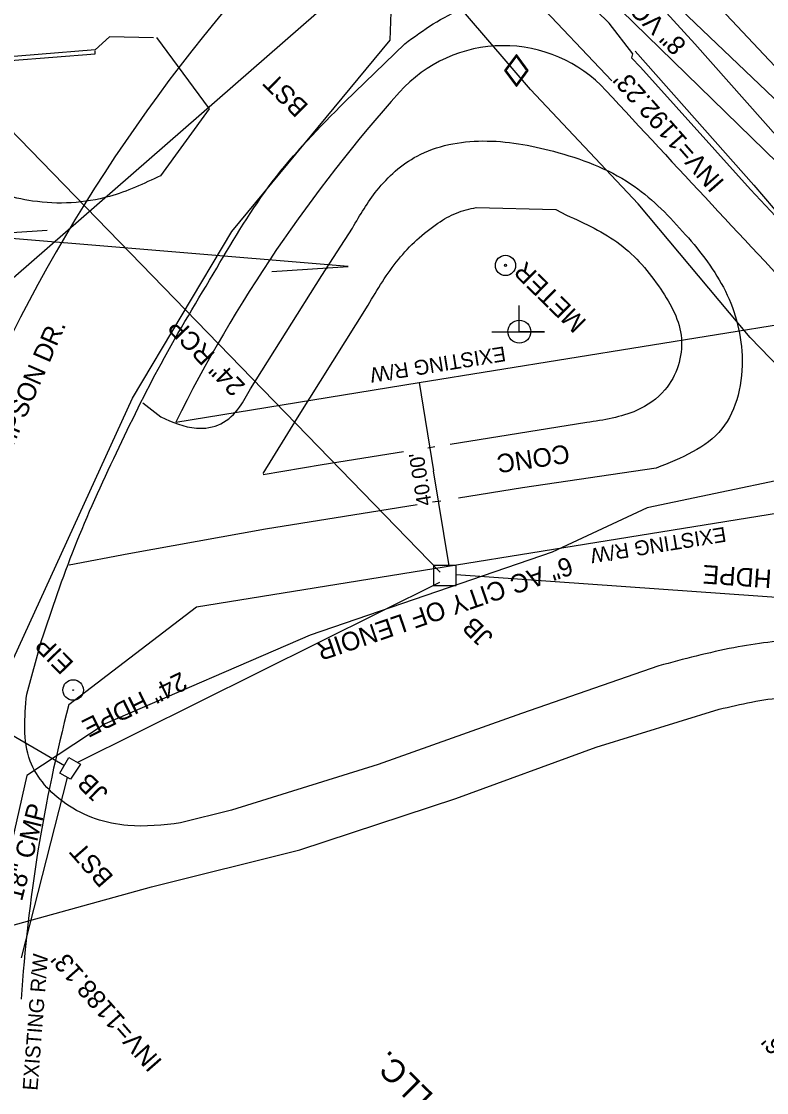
# Model space of a CAD drawing. Extents: x 1263837 to 1268319, y 770628 to 773628.
# Drawn here: x 1266461.1 to 1266621.4, y 771971.5 to 772202.1 of the extents above; entities that cross this region are included whole.
import ezdxf

# ---------------------------------------------------------------- set-up
doc = ezdxf.new("R2010")
doc.units = 0
for name, color, linetype in [('Exist Building', 7, 'Continuous'), ('Exist Property Iron Pin Text', 7, 'Continuous'), ('Exist Property Same Owner Line CELL', 7, 'Continuous'), ('Exist Roads EOP Other', 7, 'Continuous'), ('Exist Roads EOP Other Text', 7, 'Continuous'), ('Exist Roads EOP Text', 7, 'Continuous'), ('Exist Roads EOT Text', 7, 'Continuous'), ('Exist Structure Minor Catch Basin Top Elevation', 7, 'Continuous'), ('Exist Structure Minor Junction Box', 7, 'Continuous'), ('Exist Structure Minor Junction Box Text', 7, 'Continuous'), ('Exist Structure Minor Pipes HDPE 24 Inch', 7, 'Continuous'), ('Exist Structure Minor Pipes HDPE 24 Inch Text', 7, 'Continuous'), ('Exist Structure Minor Pipes RCP 24 Inch', 7, 'Continuous'), ('Exist Structure Minor Pipes RCP 24 Inch Text', 7, 'Continuous'), ('Exist Utilities Gas UG Line SUE LOS B', 7, 'Continuous'), ('Exist Utilities Gas UG Line SUE LOS C', 7, 'Continuous'), ('Exist Utilities Gas Valve CELL', 7, 'Continuous'), ('Exist Utilities Other Located Object CELL', 7, 'Continuous'), ('Exist Utilities Other Located Object Text', 7, 'Continuous'), ('Exist Utilities Power Joint Use Telephone CELL', 7, 'Continuous'), ('Exist Utilities Water UG Line SUE LOS B', 7, 'Continuous'), ('Exist Utilities Water UG Line SUE LOS B Text', 7, 'Continuous'), ('Prop Conc 4in Sidewalk', 7, 'Continuous'), ('Prop Drainage Structure Pipe Alternate 42in Label', 7, 'Continuous'), ('Prop Drainage Structure Pipe RCP 30in Class III Label', 7, 'Continuous'), ('Prop Drainage Structure Pipe RCP 42in Class III', 7, 'Continuous'), ('Prop Drainage Structure Plot Symbol 20 Scale CELL', 7, 'Continuous'), ('Prop Earthen Structure Base Ditch Special Cut with Rip Rap Detail CELL', 7, 'Continuous'), ('Prop Earthen Structure V Ditch Special Lateral with Rip Rap Detail CELL', 7, 'Continuous'), ('Prop Horizontal Alignment', 7, 'Continuous'), ('Prop SS Fill Text', 7, 'Continuous'), ('Prop SS Transition Line', 7, 'Continuous'), ('Scratch_Level_0', 7, 'Continuous'), ('Scratch_Level_2', 7, 'Continuous'), ('Scratch_Level_5', 7, 'Continuous')]:
    doc.layers.add(name, color=color, linetype=linetype)

# ---------------------------------------------------------------- blocks, each defined once
blk = doc.blocks.new('EXIST PROPERTY IRON PIN')
at = {"layer": 'Prop Conc 4in Sidewalk'}
for radius in [0.0441, 0.00141]:
    blk.add_circle((0, 0), radius, dxfattribs=at)
blk = doc.blocks.new('EXIST UTILITIES POWER JOINT USE TELEPHONE')
at = {"layer": 'Exist Utilities Power Joint Use Telephone CELL'}
blk.add_line((0, 0), (0, 0), dxfattribs=at)
blk.add_lwpolyline([(-0.1188, 0), (0.108, -0.0008), (0, -0.0004), (0, 0.1125)], dxfattribs=at)
blk.add_circle((0, 0.0001), 0.049, dxfattribs=at)
blk = doc.blocks.new('EXIST UTILITIES GAS VALVE')
at = {"layer": 'Exist Utilities Gas Valve CELL'}
blk.add_line((0, 0), (0, 0), dxfattribs=at)
blk.add_lwpolyline([(0, 0.0683), (-0.0508, 0), (0, -0.0683), (0.0508, 0), (0, 0.0683)], dxfattribs=at)
blk.add_lwpolyline([(0.0458, 0), (0, 0.0615), (-0.0458, 0), (0, -0.0615)], close=True, dxfattribs=at)

msp = doc.modelspace()

# ---------------------------------------------------------------- linework, layer by layer
at = {"layer": 'Exist Building'}
msp.add_lwpolyline([(1266342.06, 772185.13), (1266342.08, 772184.54), (1266374.13, 772186.64), (1266407.27, 772189.04), (1266438.37, 772191.77), (1266458.75, 772193.68), (1266476.96, 772195.16), (1266476.92, 772195.76)], dxfattribs=at)
at = {"layer": 'Exist Property Same Owner Line CELL'}
msp.add_lwpolyline([(1266514.94, 772148.26), (1266531.34, 772149.34), (1266450.24, 772156.1), (1266466.63, 772157.18)], dxfattribs=at)
at = {"layer": 'Exist Roads EOP Other'}
for p, q in [((1266558.93, 772162.08), (1266576.01, 772161.65)), ((1266576.01, 772161.65), (1266578.36, 772160.42)), ((1266525.69, 772147.43), (1266532.28, 772157.65)), ((1266510.32, 772123.05), (1266525.69, 772147.43)), ((1266487.17, 772119.99), (1266491.09, 772116.97))]:
    msp.add_line(p, q, dxfattribs=at)
for points in [[(1266513.08, 772104.83), (1266520.46, 772116.81), (1266535.65, 772141.04)], [(1266582.68, 772115.76), (1266553.29, 772111.06)], [(1266543.25, 772109.45), (1266525.78, 772106.66), (1266513.11, 772104.55)], [(1266550.02, 772110.53), (1266548.5, 772110.29)], [(1266597.62, 772105.95), (1266568.85, 772101.69), (1266555.13, 772099.5)], [(1266546.23, 772098.07), (1266538.18, 772096.78), (1266513.57, 772092.83), (1266484.19, 772087.52), (1266471.34, 772085.06)], [(1266551.27, 772098.88), (1266549.54, 772098.6)]]:
    msp.add_lwpolyline(points, dxfattribs=at)
for points in [[(1266532.28, 772157.65), (1266537.56, 772165.75), (1266546.19, 772173.14), (1266560.29, 772176.38), (1266575.57, 772174.16), (1266592.13, 772167.17), (1266603.32, 772156.92), (1266612.09, 772144.88), (1266616.12, 772130.18), (1266611.75, 772114.39), (1266597.62, 772105.95)], [(1266535.65, 772141.04), (1266542.18, 772150.88), (1266550.67, 772158.68), (1266554.64, 772160.87), (1266558.93, 772162.08)], [(1266578.36, 772160.42), (1266589.8, 772154.19), (1266598.61, 772144.5), (1266603.07, 772133.85), (1266599.52, 772122.82), (1266593.43, 772118.38), (1266582.68, 772115.76)], [(1266491.09, 772116.97), (1266498.71, 772114.56), (1266503.97, 772115.5), (1266508, 772119.08), (1266510.32, 772123.05)]]:
    msp.add_spline(points, degree=3, dxfattribs=at)
at = {"layer": 'Exist Structure Minor Junction Box'}
msp.add_lwpolyline([(1266549.75, 772085.02), (1266549.75, 772080.7), (1266554.62, 772080.7), (1266554.62, 772085.02)], close=True, dxfattribs=at)
msp.add_lwpolyline([(1266469.34, 772040.28), (1266471.25, 772043.64), (1266473.76, 772042.21), (1266471.64, 772038.98), (1266469.34, 772040.28)], dxfattribs=at)
at = {"layer": 'Exist Structure Minor Pipes HDPE 24 Inch'}
for p, q in [((1266694.5, 772073.08), (1266554.62, 772082.96)), ((1266551.03, 772081.34), (1266473.12, 772042.57))]:
    msp.add_line(p, q, dxfattribs=at)
at = {"layer": 'Exist Structure Minor Pipes RCP 24 Inch'}
msp.add_line((1266455.77, 772181.85), (1266551.14, 772083.59), dxfattribs=at)
at = {"layer": 'Exist Utilities Gas UG Line SUE LOS B'}
msp.add_line((1266542.76, 772219.73), (1266372.53, 772071.1), dxfattribs=at)
msp.add_lwpolyline([(1266634.89, 772116.41), (1266617.88, 772134.08), (1266593.74, 772162.87), (1266570.59, 772187.5), (1266552.2, 772208.93), (1266533.9, 772229.88), (1266520.79, 772243.67), (1266506.09, 772258.4), (1266476.3, 772293.88), (1266450.61, 772322.46), (1266432.17, 772342.72), (1266403.52, 772374.96), (1266376.24, 772400.79), (1266349.14, 772427.18), (1266329.27, 772447.31), (1266306.87, 772470.18), (1266286, 772492.58), (1266264.53, 772515.83), (1266241.63, 772542.64), (1266214.18, 772573.35), (1266190.07, 772598.41)], dxfattribs=at)
at = {"layer": 'Exist Utilities Gas UG Line SUE LOS C'}
msp.add_lwpolyline([(1266457.07, 772059.93), (1266485, 772121.03), (1266506.31, 772156.87), (1266540.43, 772198.08), (1266541.09, 772218.23), (1266505.13, 772257.1), (1266475.32, 772292.21), (1266449.64, 772321.32), (1266402.45, 772373.22), (1266377.36, 772397.1)], dxfattribs=at)
at = {"layer": 'Exist Utilities Other Located Object CELL'}
for radius in [2.18, 0.24]:
    msp.add_circle((1266565.21, 772149.59), radius, dxfattribs=at)
at = {"layer": 'Exist Utilities Water UG Line SUE LOS B'}
for points in [[(1266813.73, 772072.54), (1266793.78, 772088.05), (1266755.27, 772103.69), (1266718.33, 772109.44), (1266678.54, 772111.01), (1266653.19, 772143.96), (1266605.92, 772197.31), (1266538.03, 772271.69), (1266479.88, 772335.62), (1266421.78, 772389.51), (1266357.3, 772412.97), (1266321.15, 772412.43), (1266255.77, 772387.79), (1266212.97, 772357.83), (1266212.08, 772352.35), (1266208.85, 772350.26), (1266194.96, 772350.29), (1266178.01, 772373.6), (1266155.19, 772357.9), (1266088.3, 772309.2), (1266057.71, 772286.98)], [(1266678.5, 772110.69), (1266675.2, 772110.12), (1266640.79, 772106.85), (1266595.72, 772097.39), (1266575.28, 772087.89), (1266523.2, 772069.98), (1266479.12, 772050.94), (1266462.23, 772039.82), (1266457.93, 772020.72)]]:
    msp.add_lwpolyline(points, dxfattribs=at)
at = {"layer": 'Prop Drainage Structure Pipe Alternate 42in Label'}
for p in [(1266546.66, 772124.37), (1266553.06, 772084.89)]:
    msp.add_line(p, (1266549.74, 772105.4), dxfattribs=at)
at = {"layer": 'Prop Drainage Structure Pipe RCP 42in Class III'}
for p, q in [((1266588.07, 772189.36), (1266533.1, 772247.44)), ((1266433.8, 772063.23), (1266470.3, 772041.97)), ((1266461.11, 772000.56), (1266470.97, 772039.36))]:
    msp.add_line(p, q, dxfattribs=at)
at = {"layer": 'Prop Horizontal Alignment'}
for p, q in [((1266546.66, 772124.37), (1266632.41, 772138.26)), ((1266494.27, 772115.88), (1266546.66, 772124.37)), ((1266498.73, 772076.08), (1266665.46, 772103.1)), ((1266471.29, 772055.06), (1266498.73, 772076.08))]:
    msp.add_line(p, q, dxfattribs=at)
for centre, radius, start, end in [((1266782.56, 771972.2), 362.11, 136.7494, 177.4601), ((1266564.79, 772166.9), 30, 42.7702, 138.2005), ((1266782.56, 771972.2), 322.11, 138.2005, 153.5076), ((1275094.23, 780056.99), 11589.16, 222.770156, 223.101062), ((1266792.65, 771970.57), 332.28, 165.2685, 176.3676)]:
    msp.add_arc(centre, radius, start, end, dxfattribs=at)
at = {"layer": 'Prop SS Fill Text'}
for p, q in [((1266530.66, 772184.84), (1266543.54, 772197.33)), ((1266462.21, 772057.27), (1266465.37, 772068.82))]:
    msp.add_line(p, q, dxfattribs=at)
for points in [[(1266587.62, 772201.64), (1266562.12, 772226.59), (1266538.59, 772253.06), (1266513.27, 772283.88), (1266487.36, 772315.29), (1266460.35, 772344.33), (1266436.57, 772368.38)], [(1266587.47, 772201.71), (1266592.52, 772195.14), (1266592.34, 772194.27), (1266594.23, 772192.3), (1266617.9, 772165.95), (1266628.7, 772154.43)], [(1266489.46, 772198.62), (1266480, 772198.81), (1266476.92, 772196.02), (1266452.35, 772193.98), (1266423.43, 772191.61), (1266392.73, 772189.26), (1266361.1, 772186.81), (1266342.73, 772185.49), (1266342.04, 772185.96), (1266337.52, 772184.78), (1266335.64, 772184.84)], [(1266490.12, 772198.63), (1266501.47, 772183.28), (1266491, 772168.88)], [(1266598.19, 772063.4), (1266568.65, 772053.15), (1266537.84, 772042.16), (1266506.3, 772032.32), (1266495.32, 772029.58)], [(1266450.9, 772002.14), (1266458.25, 772007.25), (1266489.04, 772015.83), (1266520.98, 772023.81), (1266554.52, 772034.84), (1266584.69, 772045.86), (1266611.17, 772054.05)]]:
    msp.add_lwpolyline(points, dxfattribs=at)
for points in [[(1266543.54, 772197.33), (1266556.22, 772204.95), (1266570.23, 772207.07), (1266577.76, 772206.37), (1266581.24, 772205.97)], [(1266465.37, 772068.82), (1266472.54, 772088.99), (1266481.52, 772109.28), (1266491.12, 772128.44), (1266503.08, 772149), (1266515.04, 772167.58), (1266530.66, 772184.84)], [(1266491, 772168.88), (1266480, 772164.45), (1266463.48, 772163.46), (1266450.29, 772167.25), (1266440.92, 772171.31)], [(1266658.69, 772063.76), (1266644.43, 772068.13), (1266629.06, 772069.08), (1266614.37, 772067.3), (1266598.19, 772063.4)], [(1266495.32, 772029.58), (1266483.96, 772029.02), (1266470.63, 772033.71), (1266462.96, 772042.9), (1266462.21, 772057.27)], [(1266611.17, 772054.05), (1266625.21, 772056.6), (1266639.53, 772055.91), (1266653.66, 772052.68), (1266669.82, 772045.64)]]:
    msp.add_spline(points, degree=3, dxfattribs=at)
at = {"layer": 'Prop SS Transition Line'}
for points in [[(1266629.01, 772179.81), (1266601.41, 772206.09), (1266581.53, 772226.99)], [(1266593.13, 772195.71), (1266618.67, 772166.89), (1266629.01, 772154.67)]]:
    msp.add_lwpolyline(points, dxfattribs=at)
at = {"layer": 'Scratch_Level_2'}
msp.add_line((1266455.87, 772370.42), (1266643.95, 772170.37), dxfattribs=at)
msp.add_arc((1275094.23, 780056.99), 11459.16, 216.983333, 225.433333, dxfattribs=at)
at = {"layer": 'Scratch_Level_5'}
msp.add_line((1266683.36, 772113.38), (1266386.71, 772403.16), dxfattribs=at)

# ---------------------------------------------------------------- block references
at = {"layer": 'Exist Utilities Gas Valve CELL', "xscale": 50, "yscale": 50}
msp.add_blockref('EXIST UTILITIES GAS VALVE', (1266567.55, 772191.56), dxfattribs=at)
at = {"layer": 'Exist Utilities Power Joint Use Telephone CELL', "xscale": 50, "yscale": 50}
msp.add_blockref('EXIST UTILITIES POWER JOINT USE TELEPHONE', (1266568.19, 772135.33), dxfattribs=at)
at = {"layer": 'Prop Conc 4in Sidewalk', "xscale": 50, "yscale": 50}
msp.add_blockref('EXIST PROPERTY IRON PIN', (1266472.19, 772058.19), dxfattribs=at)

# ---------------------------------------------------------------- texts
at = {"layer": 'Exist Property Iron Pin Text'}
msp.add_text('EIP', height=4, rotation=134.4607, dxfattribs=at).set_placement((1266472.54, 772064.01))
at = {"layer": 'Exist Roads EOP Other Text'}
msp.add_text('CONC', height=4, rotation=188.4184, dxfattribs=at).set_placement((1266578.69, 772111.11))
at = {"layer": 'Exist Roads EOP Text'}
for s, rotation, p in [('SR 1952 (PINE MOUNTAIN RD.)', 137.8051, (1266670.04, 772168.52)), ('THOMPSON DR.', 66.4917, (1266454.14, 772098.72))]:
    msp.add_text(s, height=4, rotation=rotation, dxfattribs=at).set_placement(p)
at = {"layer": 'Exist Roads EOT Text'}
for rotation, p in [(135.4239, (1266523.03, 772184.02)), (131.3556, (1266481.08, 772017.99))]:
    msp.add_text('BST', height=4, rotation=rotation, dxfattribs=at).set_placement(p)
at = {"layer": 'Exist Structure Minor Catch Basin Top Elevation'}
msp.add_text("TOP=1185.96'", height=4, rotation=131.3556, dxfattribs=at).set_placement((1266645.74, 771958.98))
at = {"layer": 'Exist Structure Minor Junction Box Text'}
for p in [(1266562.8, 772069.84), (1266479.97, 772036.26)]:
    msp.add_text('JB', height=4, rotation=135.4239, dxfattribs=at).set_placement(p)
at = {"layer": 'Exist Structure Minor Pipes HDPE 24 Inch Text'}
for rotation, p in [(175.9601, (1266631.91, 772083.42)), (206.453, (1266495.4, 772062.23))]:
    msp.add_text('24" HDPE', height=4, rotation=rotation, dxfattribs=at).set_placement(p)
at = {"layer": 'Exist Structure Minor Pipes RCP 24 Inch Text'}
msp.add_text('24" RCP', height=4, rotation=134.1434, dxfattribs=at).set_placement((1266509.45, 772123.83))
at = {"layer": 'Exist Utilities Other Located Object Text'}
msp.add_text('METER', height=4, rotation=135.4239, dxfattribs=at).set_placement((1266582.84, 772137.59))
at = {"layer": 'Exist Utilities Water UG Line SUE LOS B Text'}
msp.add_text('6" AC CITY OF LENOIR', height=4, rotation=198.9804, dxfattribs=at).set_placement((1266578.84, 772087))
at = {"layer": 'Prop Drainage Structure Pipe Alternate 42in Label'}
msp.add_text("40.00'", height=3.2, rotation=99.2033, dxfattribs=at).set_placement((1266549.38, 772098.09))
at = {"layer": 'Prop Drainage Structure Pipe RCP 30in Class III Label'}
msp.add_text('18" CMP', height=4, rotation=75.7363, dxfattribs=at).set_placement((1266461.17, 772012.57))
at = {"layer": 'Prop Drainage Structure Plot Symbol 20 Scale CELL'}
for s, p in [("INV=1192.23'", (1266612.5, 772167.6)), ("INV=1188.13'", (1266491.55, 771978.26))]:
    msp.add_text(s, height=4, rotation=131.3556, dxfattribs=at).set_placement(p)
at = {"layer": 'Prop Earthen Structure Base Ditch Special Cut with Rip Rap Detail CELL'}
msp.add_text('HUNTLEY & WATERS, LLC.', height=5, rotation=135.4239, dxfattribs=at).set_placement((1266601.03, 771920.65))
at = {"layer": 'Prop Earthen Structure V Ditch Special Lateral with Rip Rap Detail CELL'}
for rotation, p in [(189.2033, (1266564.97, 772132.2)), (189.2033, (1266612.39, 772093.33)), (85.5659, (1266464.51, 771971.89))]:
    msp.add_text('EXISTING R/W', height=3.2, rotation=rotation, dxfattribs=at).set_placement(p)
at = {"layer": 'Scratch_Level_0'}
msp.add_text('8" VCP CITY OF LENOIR', height=4, rotation=135.6706, dxfattribs=at).set_placement((1266604.37, 772197.36))

doc.saveas('drawing.dxf')
